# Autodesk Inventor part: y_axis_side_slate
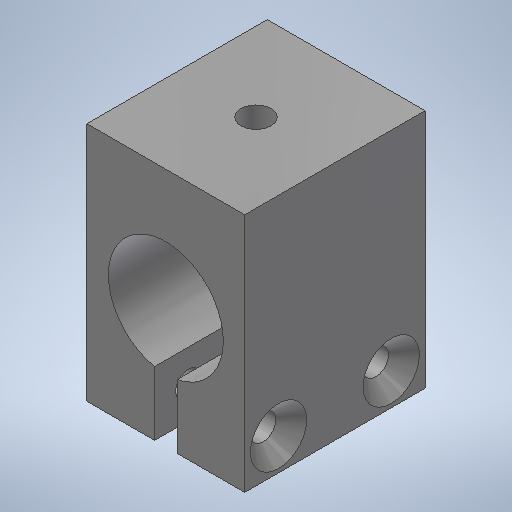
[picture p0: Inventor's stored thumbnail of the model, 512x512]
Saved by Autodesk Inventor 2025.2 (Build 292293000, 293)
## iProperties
Created: 2025-04
Part Number: y_axis_side_slate
Material: 1.0037 S235JR
Document SubType Name: Modeling
Designer: BennF
Density: 7.85 g/cm^3
Appearance: Stahl
Author: BennF
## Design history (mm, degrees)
sketch "Sketch2"
  geometry: L1 (10.5, 16)-(-10.5, 16); L2 (-10.5, 16)-(-10.5, -16); L3 (-10.5, -16)-(10.5, -16); L4 (10.5, -16)-(10.5, 16); 3 further points
  constraints: 8 end point, 2 midpoint, 2 parallel, 1 horizontal, 1 horizontal alignment, 1 perpendicular, 1 vertical alignment
  dimensions: "d0" = 21 distance of L2.end L3.end; "d1" = 32 distance of L3.end L1.start
extrude "Extrusion1" new body sketch "Sketch2" distance "d2" = 24; taper "d3" = 0 deg
sketch "Sketch3"
  geometry: L1 (-1.5, -7.501)-(-1.5, -16); L2 (10.5, -16)-(-10.5, -16) reference; L3 (1.5, -7.501)-(1.5, -16); A1 r 7.65 centre (0, 0) between (1.5, -7.501) and (-1.5, -7.501); 1 further point
  constraints: 4 end point, 2 point on circle, 2 point on line, 1 centre point, 1 coincident, 1 horizontal alignment, 1 parallel, 1 vertical
  dimensions: "d5" = 7.65 radius of A1; "d6" = 3 distance between parallel lines of L3 L1; "d28" = 16 distance from line of L2 A1.centre
extrude "Extrusion2" cut sketch "Sketch3" stored distance "d7" = 24; taper "d8" = 0 deg
sketch "Sketch4"
  geometry: L1 (27.751, 4.5)-(27.751, 19.5); L2 (32, 0)-(32, 24) reference; L3 (32, 0)-(23.501, 0) reference; 4 further points
  constraints: 3 midpoint, 2 end point, 1 horizontal alignment, 1 vertical, 1 vertical alignment
  dimensions: "d16" = 15 distance of L1.start L1.end
hole "Hole1" sketch "Sketch4" at (27.751, 4.5), (27.751, 19.5) diameter "d9" = 3.4; stored, may be unused: countersink angle "d13" = 90 deg, drill point angle "d15" = 0 deg; dims "d10" = 6, "d11" = 7.5, "d12" = 2, "d14" = 20
workplane "Work Plane1"
sketch "Sketch5"
  geometry: L1 (1.074, 19.5)-(2.662, 22.25); L2 (2.662, 22.25)-(5.837, 22.25); L3 (5.837, 22.25)-(7.425, 19.5); L4 (7.425, 19.5)-(5.837, 16.75); L5 (5.837, 16.75)-(2.662, 16.75); L6 (2.662, 16.75)-(1.074, 19.5); L7 (1.074, 4.5)-(2.662, 7.25); L8 (2.662, 7.25)-(5.837, 7.25); L9 (5.837, 7.25)-(7.425, 4.5); L10 (7.425, 4.5)-(5.837, 1.75); L11 (5.837, 1.75)-(2.662, 1.75); L12 (2.662, 1.75)-(1.074, 4.5); L13 (5.837, 22.25)-(8.499, 22.25); L14 (5.837, 16.75)-(8.499, 16.75); L15 (8.499, 24)-(8.499, 0) reference; L16 (5.837, 7.25)-(8.499, 7.25); L17 (8.499, 0)-(8.499, 24) reference; L18 (5.837, 1.75)-(8.499, 1.75); C1 r 1.7 at (4.249, 19.5) reference; C2 r 1.7 at (4.249, 4.5) reference; 5 further points
  constraints: 32 end point, 4 point on line, 3 horizontal, 2 coincident, 2 horizontal alignment, 1 equal length, 1 perpendicular, 26 other
  dimensions: "d18" = 5.5 distance between parallel lines of L5 L2
extrude "Extrusion3" cut sketch "Sketch5" distance "d19" = 2.5; taper "d20" = 0 deg
sketch "Sketch6"
  geometry: L1 (21, 0)-(21, 24) reference; L2 (0, 0)-(21, 0) reference; 4 further points
  constraints: 2 midpoint, 1 horizontal alignment, 1 vertical alignment
hole "Hole2" sketch "Sketch6" at (10.5, 12) diameter "d21" = 3.2; stored, may be unused: countersink angle "d25" = 90 deg, drill point angle "d27" = 0 deg; dims "d22" = 6, "d23" = 4, "d24" = 6.7, "d26" = 8
body "Solid1"
other parameters: "d17" = -3
